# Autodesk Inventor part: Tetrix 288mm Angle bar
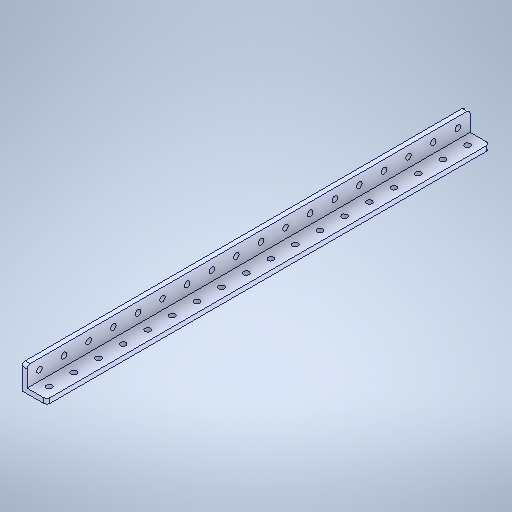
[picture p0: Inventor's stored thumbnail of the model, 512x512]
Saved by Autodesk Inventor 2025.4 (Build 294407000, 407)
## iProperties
Created: 2021-10
Part Number: Tetrix 288mm Angle bar
Material: Genérico
Document SubType Name: Modeling
Designer: usuario
Density: 1 g/cm^3
Appearance: Valor por defecto
Author: usuario
Sending System: SolidWorks 2016
Last Author: LENOVO
Last Saved: 2021-10-21
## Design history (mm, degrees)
fillet "Fillet1"
node "Plane1"
node "Sólido1"
